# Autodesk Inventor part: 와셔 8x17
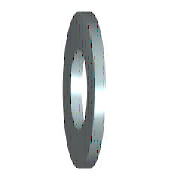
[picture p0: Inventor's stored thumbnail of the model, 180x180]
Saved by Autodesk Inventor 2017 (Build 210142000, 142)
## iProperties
IsCustomPart: 1
Created: 2012-02
Part Number: 와셔 8x17
Material: 강철, 연강
Description: 평면 와셔
Document SubType Name: Modeling
Standard: KS B 1326
Designer: mduedu
Standards Organization: KS
Language: ko-KR
Size Designation: 8x17
Categories: <MemberInstance><Categories><Category DisplayName="조임쇠" InternalName="e4da775c-781d-43d5-af7c-5136215cf5a6" Mnemonic="FSTN"><Category DisplayName="와셔" InternalN
Density: 1 g/cm^3
Appearance: 주황색
Author: mduedu
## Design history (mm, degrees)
sketch "스케치"
  geometry: C1 r 8.5 at (0, 0); C2 r 4.2 at (0, 0); 1 further point
  constraints: 2 centre point, 2 coincident
  dimensions: "d0" = 8.4 diameter of C2 (= SD1); "d1" = 17 diameter of C1 (= SD2)
extrude "본체" new body sketch "스케치" distance "d2" = 1.6 (= SD); taper "d3" = 0 deg
workaxis "Work Axis1"
workplane "Work Plane1"
body "Solid1"
other parameters: "SD1" = 8.4 [user parameter; used in 1 equation term], "SD2" = 17 [user parameter; used in 1 equation term], "SD" = 1.6 [user parameter; used in 1 equation term], "d4" = 0, "d5" = 0, "d6" = 0, "d7" = 0, "NND" = 8 [user parameter]
